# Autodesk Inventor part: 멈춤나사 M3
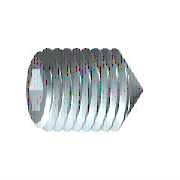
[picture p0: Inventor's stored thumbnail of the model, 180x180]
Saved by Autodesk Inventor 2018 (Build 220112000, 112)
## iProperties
IsCustomPart: 1
Created: 2012-02
Part Number: 멈춤나사 M3
Material: 강철, 연강
Description: 6각 소켓 머리 없는 멈춤 나사
Document SubType Name: Modeling
Standard: KS B 1028
Designer: mduedu
Standards Organization: KS
Language: ko-KR
Size Designation: 원추점 M3x6
Categories: <MemberInstance><Categories><Category DisplayName="조임쇠" InternalName="e4da775c-781d-43d5-af7c-5136215cf5a6" Mnemonic="FSTN"><Category DisplayName="볼트" InternalN
Density: 1 g/cm^3
Appearance: 노란색
Author: mduedu
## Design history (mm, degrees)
sketch "스케치1"
  geometry: L1 (0, 0)-(3.5, 0); L2 (6, 0.866)-(6, 1.5); L3 (6, 1.5)-(0, 1.5); L4 (6, 0.866)-(4, 0.866); L5 (4, 0.866)-(3.5, 0); L6 (0, -0.3)-(0, 1.8) reference; L7 (0, 1.5)-(0, 0)
  constraints: 13 end point, 3 parallel, 1 collinear, 1 perpendicular, 1 point on line
  dimensions: "d0" = 2 distance of L2.start L4.end (= INTI); "d1" = 60 deg angle of L5 L1; "d2" = 3 diameter of L3 L1 (= NND); "d3" = 1.73205 diameter of L4 L1 (= 1.1547 x SW); "d5" = 6 distance from line of L2 L3.end (= NLG)
revolve "본체" sketch "스케치1" stored, may be unused: angle "d6" = 90 deg
sketch "스케치2"
  geometry: L1 (-0.433, 0.75)-(0.433, 0.75); L2 (0.433, 0.75)-(0.866, 0); L3 (0.866, 0)-(0.433, -0.75); L4 (0.433, -0.75)-(-0.433, -0.75); L5 (-0.433, -0.75)-(-0.866, 0); L6 (-0.866, 0)-(-0.433, 0.75); 3 further points
  constraints: 12 end point, 1 coincident, 1 horizontal, 13 other
extrude "슬롯" join sketch "스케치2" taper "d7" = 0 deg; stored distance "d21" = 10
workaxis "Work Axis1"
workplane "Work Plane1"
body "Solid1"
feature "스레드" dims "d12" = 6 (= NLG), "d13" = 0
chamfer "모따기1" distance "d8" = 1.35 (computed from NND, SPD, FAWI); stored, may be unused: angle "d9" = 45 deg (= FAWI), second distance "d34" = 1.35 (computed from NND, SPD, FAWI)
chamfer "모따기2" distance "d10" = 0.30673 (= -0.5 x GD1 + 0.5 x NND); stored, may be unused: angle "d11" = 45 deg (= FAWI), second distance "d35" = 0.30673 (= -0.5 x GD1 + 0.5 x NND)
other parameters: "NND" = 3 [user parameter; used in 5 equation terms], "NLG" = 6 [user parameter; used in 2 equation terms], "INTI" = 2 [user parameter; used in 1 equation term], "FAWI" = 45 deg [user parameter; used in 4 equation terms], "SW" = 1.5 [user parameter; used in 2 equation terms], "GD1" = 2.38655 (= THREADDIA - 1.2269 x PTC) [user parameter; used in 2 equation terms], "d4" = 0, "FAWI1" = 45 deg [user parameter], "SPD" = 0.3 [user parameter; used in 2 equation terms], "d36" = 0, "d37" = 0, "GUL" = 0.30673 (= 0.61345 x PTC) [user parameter], "TOA" = 30 deg [user parameter], "THREADDIA" = 3 [user parameter; used in 1 equation term], "PTC" = 0.5 [user parameter; used in 4 equation terms], "GAL" = 0.30673 (= 0.61345 x PTC) [user parameter], "E0" = 1.7325 (= 1.155 x SW) [user parameter]
